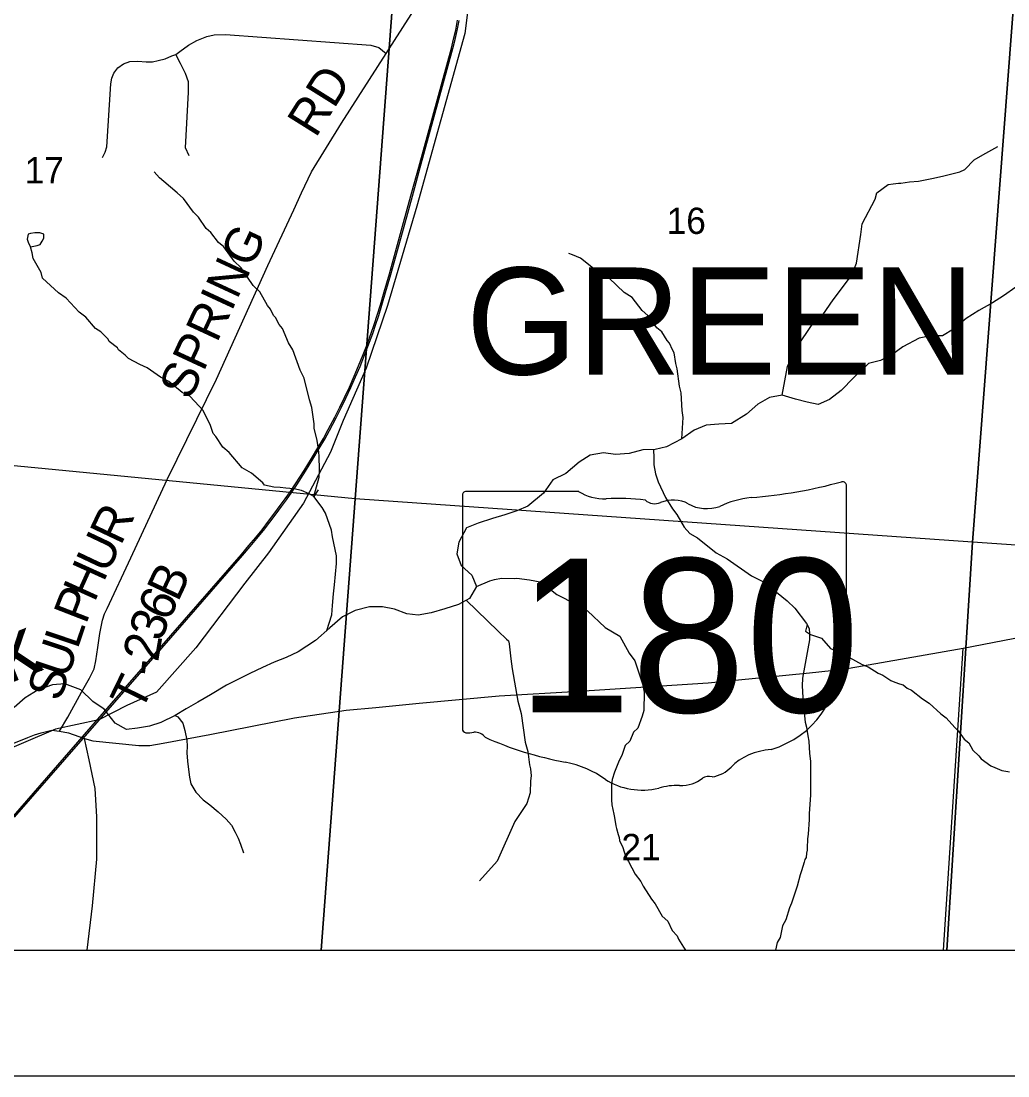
# Model space of a CAD drawing. Extents: x 0 to 42.5, y 0 to 22.
# Drawn here: x 2.796 to 3.582, y 14 to 14.84 of the extents above; entities that cross this region are included whole.
import ezdxf

# ---------------------------------------------------------------- set-up
doc = ezdxf.new("R2010")
doc.units = 0
for name, color, linetype in [('GM_X_County_Road', 7, 'Continuous'), ('GM_X_Interchange_Ramps', 7, 'Continuous'), ('GM_X_Minor_Lake', 7, 'Continuous'), ('GM_X_Minor_River', 7, 'Continuous'), ('GM_X_Minor_River_Text', 7, 'Continuous'), ('GM_X_Rail_Line', 7, 'Continuous'), ('GM_X_Section', 7, 'Continuous'), ('GM_X_Section_Text', 7, 'Continuous'), ('GM_X_State_Location', 7, 'Continuous'), ('GM_X_State_Route', 7, 'Continuous'), ('GM_X_State_Shield', 7, 'Continuous'), ('GM_X_Township_Road', 7, 'Continuous'), ('GM_X_Township_Road_Text', 7, 'Continuous'), ('GM_X_Township_Text', 7, 'Continuous'), ('GM_X_Unincorporated', 7, 'Continuous'), ('SH_Cut_Line', 7, 'Continuous'), ('SH_Data', 7, 'Continuous')]:
    doc.layers.add(name, color=color, linetype=linetype)

msp = doc.modelspace()

# ---------------------------------------------------------------- linework, layer by layer
at = {"layer": 'GM_X_County_Road'}
msp.add_lwpolyline([(2.84846, 14.1), (2.85274, 14.13543), (2.85614, 14.17249), (2.85609, 14.20615), (2.85479, 14.2288), (2.84994, 14.25157), (2.8463, 14.26864)], dxfattribs=at)
at = {"layer": 'GM_X_Interchange_Ramps'}
msp.add_lwpolyline([(4.44374, 15.85348), (3.72132, 15.90374), (3.70364, 15.90484), (3.68116, 15.90613), (3.63539, 15.91028), (3.54426, 15.91466), (3.50878, 15.91695), (3.47339, 15.91924), (3.14954, 15.94013), (2.52965, 15.98049), (2.1, 16.00757), (2.1, 14.1), (5.08492, 14.1)], dxfattribs=at)
at = {"layer": 'GM_X_Minor_Lake'}
for points in [[(2.80875, 14.66109), (2.81103, 14.66185), (2.81255, 14.66469), (2.81408, 14.66697), (2.81389, 14.67001), (2.81086, 14.67116), (2.80687, 14.67116), (2.80345, 14.6706), (2.80136, 14.67022), (2.80078, 14.66604), (2.80173, 14.663), (2.80324, 14.65996)], [(2.80324, 14.65996), (2.80875, 14.66109)]]:
    msp.add_lwpolyline(points, dxfattribs=at)
at = {"layer": 'GM_X_Minor_River'}
for points in [[(3.40207, 14.54193), (3.4063, 14.56478), (3.40898, 14.5697), (3.41205, 14.57595), (3.41263, 14.57727), (3.41397, 14.58031), (3.42584, 14.59828), (3.43424, 14.60582), (3.44247, 14.61792), (3.4572, 14.6372), (3.46123, 14.64705), (3.46456, 14.66983), (3.46555, 14.67838), (3.47591, 14.69788), (3.47745, 14.703), (3.48623, 14.70959), (3.49022, 14.71032), (3.4946, 14.71086), (3.4965, 14.71085), (3.50335, 14.71175), (3.51058, 14.71227), (3.52238, 14.71466), (3.53057, 14.7165), (3.54352, 14.71983), (3.54752, 14.7217), (3.55497, 14.72944), (3.56164, 14.73339), (3.57365, 14.73995)], [(3.03246, 14.46654), (3.02891, 14.46117), (3.03316, 14.47672), (3.03356, 14.48261), (3.03323, 14.49344), (3.03305, 14.49667), (3.03195, 14.50428), (3.03139, 14.50714), (3.02933, 14.51532), (3.02916, 14.51912), (3.02731, 14.53225), (3.02544, 14.53834), (3.02132, 14.55547), (3.01812, 14.56195), (3.01229, 14.57815), (3.00889, 14.58368), (3.004, 14.59512), (3.00135, 14.59817), (2.99852, 14.60389), (2.99682, 14.60542), (2.99436, 14.61038), (2.99209, 14.61325), (2.98586, 14.62412), (2.98056, 14.62929), (2.97111, 14.64342), (2.96543, 14.64859), (2.9573, 14.66004), (2.95294, 14.6635), (2.94689, 14.67152), (2.94329, 14.67477), (2.93724, 14.68375), (2.93308, 14.68776), (2.92532, 14.69865), (2.92002, 14.70306), (2.9096, 14.71206), (2.90619, 14.71512), (2.90183, 14.71971)], [(3.03938, 14.35457), (3.04334, 14.3672), (3.04375, 14.37442), (3.04455, 14.38391), (3.04553, 14.39094), (3.04694, 14.40803), (3.04696, 14.41411), (3.0438, 14.42914), (3.04306, 14.43447), (3.03836, 14.44799), (3.03572, 14.45257), (3.02891, 14.46117), (3.0253, 14.46347), (3.01904, 14.46599), (3.01296, 14.46736), (3.00669, 14.46797), (3.00212, 14.46839), (2.99718, 14.46861), (2.98977, 14.47018), (2.98844, 14.47209), (2.97935, 14.47994), (2.97195, 14.48399), (2.96154, 14.49641), (2.95643, 14.50062), (2.95095, 14.50902), (2.94887, 14.51151), (2.94642, 14.51856), (2.94472, 14.52161), (2.94077, 14.52981), (2.93755, 14.53325), (2.93035, 14.54109), (2.92409, 14.54398), (2.91348, 14.5528), (2.90684, 14.55626), (2.89622, 14.56375), (2.89033, 14.56645), (2.88142, 14.57126), (2.87877, 14.57394), (2.87346, 14.57816), (2.8727, 14.57968), (2.86588, 14.58467), (2.86513, 14.58657), (2.85944, 14.59231), (2.85508, 14.595), (2.84751, 14.60418), (2.84202, 14.60802), (2.83179, 14.61911), (2.82553, 14.62352), (2.81284, 14.63501), (2.81172, 14.63958), (2.80549, 14.65064), (2.80476, 14.65521), (2.80324, 14.65996)], [(3.32206, 14.50723), (3.32301, 14.52431), (3.32228, 14.52964), (3.32139, 14.5437), (3.32027, 14.54922), (3.31843, 14.56292), (3.3173, 14.5671), (3.31582, 14.57567), (3.3145, 14.57814), (3.31224, 14.58329), (3.31034, 14.58539), (3.306, 14.59226), (3.30221, 14.59552), (3.29502, 14.60526), (3.29048, 14.60928), (3.28253, 14.61979), (3.27608, 14.62364), (3.26415, 14.63512), (3.25561, 14.63974), (3.2414, 14.65105), (3.23494, 14.65375), (3.23209, 14.65472)], [(3.58805, 14.62785), (3.57812, 14.62109), (3.56935, 14.61546), (3.55867, 14.60946), (3.54837, 14.60308), (3.53842, 14.59442), (3.52965, 14.58917), (3.52054, 14.58925), (3.51103, 14.58742), (3.49806, 14.58031), (3.4889, 14.57392), (3.48013, 14.56943), (3.47062, 14.56723), (3.45914, 14.55592), (3.44881, 14.54574), (3.43964, 14.53859), (3.43049, 14.53448), (3.42177, 14.53645), (3.41268, 14.53881), (3.40207, 14.54193), (3.3918, 14.54012), (3.38265, 14.53487), (3.37348, 14.52696), (3.36164, 14.51946), (3.35139, 14.51878), (3.34151, 14.5181), (3.33198, 14.51399), (3.32206, 14.50723), (3.30986, 14.50087), (3.30073, 14.49866), (3.29085, 14.49836), (3.28019, 14.49541), (3.26918, 14.49474), (3.25969, 14.49595), (3.24905, 14.49414), (3.24027, 14.48851), (3.22957, 14.47947), (3.21928, 14.47462), (3.21198, 14.46403), (3.19936, 14.45349), (3.1906, 14.44976), (3.18109, 14.4468), (3.17119, 14.44384), (3.15977, 14.44013), (3.15063, 14.4364), (3.14446, 14.42505), (3.14287, 14.41556), (3.14621, 14.40641), (3.15489, 14.39874), (3.15861, 14.38959), (3.15284, 14.38013), (3.14407, 14.37526), (3.13341, 14.37193), (3.12237, 14.36859), (3.11211, 14.36678), (3.103, 14.36799), (3.09316, 14.37149), (3.08368, 14.37347), (3.07343, 14.37355), (3.06201, 14.3706), (3.05172, 14.36536), (3.04178, 14.3567), (3.03031, 14.34653), (3.01657, 14.33752), (3.00704, 14.33304), (2.99752, 14.32931), (2.98799, 14.32521), (2.97808, 14.32035), (2.96855, 14.31548), (2.9594, 14.311), (2.94681, 14.3035), (2.93651, 14.2975), (2.92736, 14.29225), (2.91858, 14.287), (2.90714, 14.28139), (2.89801, 14.27842), (2.8885, 14.27698), (2.87976, 14.27591), (2.87069, 14.28092), (2.86204, 14.29202), (2.85298, 14.29817), (2.84355, 14.30737), (2.83068, 14.31203), (2.8208, 14.31135), (2.80938, 14.30726), (2.79908, 14.30088), (2.79028, 14.29335)], [(3.29935, 14.49862), (3.29967, 14.49198), (3.29965, 14.48647), (3.30095, 14.47943), (3.30321, 14.47295), (3.30905, 14.46037), (3.31452, 14.45159), (3.31812, 14.44701), (3.32378, 14.4369), (3.32851, 14.43192), (3.33439, 14.42827), (3.34937, 14.41639), (3.3581, 14.41158), (3.37763, 14.39814), (3.38769, 14.39313), (3.40588, 14.37818), (3.41213, 14.37244), (3.4214, 14.36021), (3.42347, 14.35621), (3.42383, 14.35183), (3.42383, 14.3505), (3.42362, 14.34728), (3.42226, 14.34007), (3.42128, 14.33418), (3.41817, 14.31653), (3.41776, 14.31064), (3.41865, 14.29658), (3.4192, 14.29163), (3.4203, 14.28155), (3.42142, 14.27774), (3.42234, 14.27071), (3.42309, 14.26652), (3.42361, 14.25664), (3.42454, 14.25055), (3.42442, 14.22338), (3.42341, 14.20894), (3.42339, 14.20419), (3.42258, 14.19242), (3.42218, 14.18862), (3.42196, 14.1814), (3.42176, 14.17969), (3.42137, 14.17722), (3.42098, 14.174), (3.42002, 14.17229), (3.41944, 14.17021), (3.41732, 14.16319), (3.41616, 14.16016), (3.41384, 14.15105), (3.41268, 14.14707), (3.40941, 14.1374), (3.40787, 14.1338), (3.40479, 14.12432), (3.4021, 14.1194), (3.40035, 14.1101), (3.39805, 14.10613), (3.39654, 14.1)], [(3.15861, 14.38959), (3.16917, 14.39426), (3.17278, 14.39519), (3.1785, 14.39629), (3.18877, 14.39603), (3.19067, 14.39639), (3.20074, 14.395), (3.21062, 14.39303), (3.21233, 14.39111), (3.22237, 14.38325), (3.22788, 14.38055), (3.24021, 14.37401), (3.24685, 14.37016), (3.26106, 14.35695), (3.27263, 14.35022), (3.27999, 14.33668), (3.28472, 14.33057), (3.29072, 14.31209), (3.29203, 14.30543), (3.29177, 14.29099), (3.29042, 14.28644), (3.28696, 14.27696), (3.28352, 14.27357), (3.28064, 14.26656), (3.27682, 14.26316), (3.27431, 14.25501), (3.27201, 14.25123), (3.26836, 14.24194), (3.26662, 14.23587), (3.26603, 14.23189), (3.26598, 14.21972), (3.26635, 14.21573), (3.26784, 14.20831), (3.26839, 14.20565), (3.26951, 14.19918), (3.27007, 14.19708), (3.27138, 14.19213), (3.27213, 14.18985), (3.2725, 14.18738), (3.27514, 14.18185), (3.27739, 14.17423), (3.27966, 14.1706), (3.28475, 14.16069), (3.28948, 14.15476), (3.29136, 14.15114), (3.29778, 14.14084), (3.30081, 14.13701), (3.30628, 14.12728), (3.31102, 14.12307), (3.31441, 14.11583), (3.3182, 14.11162), (3.31933, 14.10895), (3.32329, 14.10246), (3.32498, 14.1)], [(3.15021, 14.37867), (3.17584, 14.35412), (3.18247, 14.34762), (3.18399, 14.34628), (3.18455, 14.34399), (3.18583, 14.33201), (3.18693, 14.32402), (3.19139, 14.29834), (3.19401, 14.28844), (3.19733, 14.26561), (3.19939, 14.25838), (3.20068, 14.24773), (3.20162, 14.24449), (3.20197, 14.23898), (3.20158, 14.23499), (3.20115, 14.2253), (3.19865, 14.21696), (3.18907, 14.20258), (3.17487, 14.17095), (3.16091, 14.15527)], [(3.42185, 14.35935), (3.42042, 14.35414), (3.4244, 14.35145), (3.43314, 14.34854), (3.44052, 14.34032), (3.45115, 14.33587), (3.45494, 14.33338), (3.46576, 14.3276), (3.47032, 14.32567), (3.47847, 14.32067), (3.48208, 14.31894), (3.48853, 14.31471), (3.49156, 14.31355), (3.49536, 14.31219), (3.4984, 14.31122), (3.50143, 14.30873), (3.50504, 14.307), (3.51376, 14.3001), (3.51907, 14.29683), (3.52835, 14.28821), (3.53252, 14.28496), (3.53953, 14.2775), (3.54218, 14.27463), (3.5469, 14.26813), (3.5505, 14.26526), (3.55371, 14.25934), (3.55845, 14.25494), (3.56053, 14.25246), (3.56811, 14.24689), (3.57134, 14.24554), (3.57685, 14.24322), (3.5816, 14.24243), (3.58293, 14.24204)], [(2.91858, 14.287), (2.92061, 14.28596), (2.92472, 14.28089), (2.92623, 14.275), (2.92793, 14.2674), (2.92811, 14.26246), (2.92791, 14.25733), (2.92847, 14.25068), (2.92922, 14.24403), (2.92997, 14.23775), (2.93091, 14.23243), (2.93489, 14.22597), (2.94077, 14.21988), (2.94607, 14.21569), (2.95271, 14.21016), (2.95916, 14.20445), (2.96333, 14.1997), (2.96636, 14.19399), (2.96882, 14.18924), (2.97052, 14.18448), (2.97298, 14.17764)]]:
    msp.add_lwpolyline(points, dxfattribs=at)
at = {"layer": 'GM_X_Rail_Line'}
for points in [[(3.15856, 14.90389), (3.14925, 14.82993), (3.11101, 14.6923), (3.08771, 14.61323), (3.07071, 14.56354), (3.05238, 14.52177), (3.04236, 14.4966), (3.02078, 14.45585), (2.99282, 14.41635), (2.97395, 14.39221), (2.93506, 14.34093), (2.90377, 14.30558), (2.87996, 14.29483), (2.85783, 14.28359)], [(2.78968, 14.2068), (2.85703, 14.28411), (2.97137, 14.41522), (2.97733, 14.42218), (2.98275, 14.4286), (2.98782, 14.43488), (2.99297, 14.44156), (2.99798, 14.44818), (3.0022, 14.454), (3.00615, 14.45942), (3.01036, 14.46537), (3.01436, 14.47124), (3.02138, 14.48208), (3.0272, 14.4915), (3.03228, 14.50006), (3.03656, 14.50742), (3.04043, 14.5145), (3.04565, 14.52439), (3.04959, 14.53228), (3.05347, 14.54017), (3.05735, 14.54846), (3.06109, 14.55702), (3.06463, 14.56524), (3.06818, 14.57426), (3.07085, 14.58109), (3.07473, 14.59144), (3.07693, 14.59819), (3.07948, 14.60575), (3.08202, 14.61383), (3.08503, 14.62414), (3.08911, 14.63847), (3.09963, 14.67652), (3.10713, 14.70358), (3.11262, 14.72355), (3.13855, 14.81813), (3.14028, 14.82547), (3.14195, 14.83262), (3.14349, 14.84043)], [(2.79059, 14.20601), (2.85794, 14.28333), (2.97228, 14.41444), (2.97825, 14.42141), (2.98367, 14.42784), (2.98877, 14.43414), (2.99393, 14.44084), (2.99895, 14.44747), (3.00317, 14.4533), (3.00712, 14.45873), (3.01134, 14.46469), (3.01536, 14.47058), (3.0224, 14.48144), (3.02823, 14.49088), (3.03332, 14.49946), (3.03761, 14.50683), (3.04149, 14.51393), (3.04672, 14.52385), (3.05067, 14.53175), (3.05456, 14.53966), (3.05844, 14.54797), (3.0622, 14.55654), (3.06575, 14.56478), (3.0693, 14.57383), (3.07198, 14.58066), (3.07586, 14.59104), (3.07807, 14.59781), (3.08062, 14.60538), (3.08317, 14.61349), (3.08618, 14.62381), (3.09027, 14.63814), (3.10079, 14.6762), (3.10829, 14.70327), (3.11378, 14.72323), (3.13971, 14.81783), (3.14145, 14.8252), (3.14313, 14.83237), (3.14467, 14.84021)], [(2.85783, 14.28359), (2.82334, 14.27594), (2.70308, 14.2249), (2.59128, 14.19074), (2.56697, 14.1766), (2.53031, 14.15072), (2.5038, 14.12969), (2.47486, 14.1)]]:
    msp.add_lwpolyline(points, dxfattribs=at)
at = {"layer": 'GM_X_Section'}
for points in [[(2.58723, 14.98757), (3.09918, 14.95159), (3.06197, 14.45953), (2.55405, 14.50856)], [(3.09918, 14.95159), (3.59088, 14.91475), (3.55348, 14.42497), (3.06197, 14.45953)], [(3.59088, 14.91475), (4.10606, 14.87895), (4.07019, 14.38934), (3.55348, 14.42497)]]:
    msp.add_lwpolyline(points, close=True, dxfattribs=at)
at = {"layer": 'GM_X_State_Route'}
for points in [[(3.07837, 14.29342), (3.11292, 14.29665), (3.17651, 14.30263), (3.24014, 14.30619), (3.34309, 14.31293), (3.42376, 14.32097), (3.45071, 14.32378), (3.54617, 14.34044), (3.61873, 14.3547), (3.77545, 14.3833), (3.81125, 14.38966)], [(2.48265, 14.16044), (2.4857, 14.16188), (2.49516, 14.16525), (2.51666, 14.17325), (2.66313, 14.21701), (2.70342, 14.23007), (2.75087, 14.24916), (2.80127, 14.26938), (2.80661, 14.27148), (2.81194, 14.27303), (2.82036, 14.27513), (2.82636, 14.27459), (2.83364, 14.27324), (2.8463, 14.26864), (2.85301, 14.26672), (2.88957, 14.26314), (2.89837, 14.26314), (2.90894, 14.26478), (2.94621, 14.27171), (3.0136, 14.28499), (3.05485, 14.29121), (3.07837, 14.29342)]]:
    msp.add_lwpolyline(points, dxfattribs=at)
at = {"layer": 'GM_X_State_Shield'}
for p, q in [((3.45313, 14.37278), (3.45313, 14.46991)), ((3.14732, 14.46211), (3.14732, 14.27643)), ((3.23989, 14.46531), (3.15033, 14.46531)), ((3.4531, 14.3728), (3.45313, 14.37278))]:
    msp.add_line(p, q, dxfattribs=at)
for centre, major_axis, start_param, end_param in [((3.34419, 14.71846), (0.32431, 0), 4.814394, 5.042369), ((3.44973, 14.47031), (0.0034, 0), 6.141152, 7.989035), ((3.15082, 14.46251), (0.00354, 0), 1.712693, 3.28349), ((3.26121, 14.48686), (0.03436, 0), 4.042523, 4.731795), ((3.27261, 14.36106), (0.12336, 0), 1.404758, 1.657858), ((3.30061, 14.46347), (0.00991, 0), 3.836095, 5.185415), ((3.31517, 14.44201), (0.02061, 0), 0.950623, 2.079405), ((3.34177, 14.47145), (0.02479, 0), 4.081561, 5.145723), ((3.38556, 14.40859), (0.06525, 0), 1.699011, 2.107814), ((3.45234, 14.36564), (0.00527, 0), 1.883978, 3.671073), ((3.44949, 14.3724), (0.00364, 0), 5.05454, 6.418171), ((3.41882, 14.35337), (0.03163, 0), 5.934695, 6.695948), ((3.46532, 14.33213), (0.02301, 0), 2.387724, 3.262537), ((3.36236, 14.31977), (0.08112, 0), 5.101752, 6.440018), ((3.15085, 14.27602), (0.00357, 0), 3.00124, 4.508301), ((3.15139, 14.29502), (0.02728, 0), 4.665946, 4.897461), ((3.15697, 14.26571), (0.00984, 0), 0.519207, 1.627899), ((3.28115, 14.43255), (0.2342, 0), 4.195997, 4.488961), ((3.39656, 14.2243), (0.04443, 0), 1.647645, 2.488434), ((3.21132, 14.19301), (0.07328, 0), 0.823519, 1.323587), ((3.34028, 14.25843), (0.02621, 0), 4.937069, 5.64225), ((3.29058, 14.26479), (0.0465, 0), 4.026481, 4.996735), ((3.32084, 14.25089), (0.02477, 0), 4.691044, 5.507374), ((3.34325, 14.2329), (0.00698, 0), 1.147584, 2.315152), ((3.31744, 14.20059), (0.03821, 0), 1.495662, 1.94098)]:
    msp.add_ellipse(centre, major_axis=major_axis, ratio=0.8, start_param=start_param, end_param=end_param, dxfattribs=at)
at = {"layer": 'GM_X_Township_Road'}
msp.add_line((3.53029, 14.1), (3.54617, 14.34044), dxfattribs=at)
for points in [[(2.82636, 14.27459), (2.83307, 14.28571), (2.844, 14.30546), (2.85033, 14.31658), (2.85397, 14.32406), (2.8555, 14.33039), (2.85685, 14.34113), (2.85857, 14.35225), (2.86068, 14.3628), (2.86222, 14.36798), (2.86433, 14.37219), (2.88322, 14.41235), (2.91231, 14.47469), (2.95147, 14.55468), (2.99239, 14.64529), (3.01311, 14.68954), (3.01929, 14.7031), (3.02725, 14.71967), (3.05108, 14.75853), (3.0867, 14.81405), (3.13311, 14.88669)], [(2.9224, 14.81549), (2.9292, 14.82056), (2.93571, 14.82437), (2.9438, 14.82755), (2.9497, 14.82882), (2.95857, 14.82898), (3.07432, 14.82072), (3.08067, 14.81882), (3.0867, 14.81405)], [(2.86061, 14.73118), (2.86283, 14.7353), (2.8641, 14.73975), (2.86744, 14.78992), (2.86823, 14.79437), (2.86982, 14.79834), (2.87299, 14.80246), (2.87744, 14.8058), (2.88236, 14.80754), (2.88871, 14.80786), (2.89538, 14.80738), (2.90046, 14.80738), (2.90507, 14.80834), (2.91062, 14.80961), (2.91602, 14.81199), (2.9192, 14.8131), (2.9224, 14.81549)], [(2.92967, 14.7326), (2.92666, 14.73895), (2.9292, 14.78309), (2.92904, 14.79135), (2.92682, 14.79817), (2.92285, 14.80596), (2.9192, 14.8131)]]:
    msp.add_lwpolyline(points, dxfattribs=at)
at = {"layer": 'GM_X_Unincorporated'}
for points in [[(2.52705, 14.1), (3.03478, 14.1), (3.06197, 14.45953), (2.55405, 14.50856)], [(3.03478, 14.1), (3.53318, 14.1), (3.55348, 14.42497), (3.06197, 14.45953)], [(3.53318, 14.1), (4.04905, 14.1), (4.07019, 14.38934), (3.55348, 14.42497)]]:
    msp.add_lwpolyline(points, close=True, dxfattribs=at)
at = {"layer": 'SH_Cut_Line'}
msp.add_lwpolyline([(4.44374, 15.85348), (3.72132, 15.90374), (3.70364, 15.90484), (3.68116, 15.90613), (3.63539, 15.91028), (3.54426, 15.91466), (3.50878, 15.91695), (3.47339, 15.91924), (3.14954, 15.94013), (2.52965, 15.98049), (2.1, 16.00757), (2.1, 14.1), (8.06989, 14.1)], dxfattribs=at)
at = {"layer": 'SH_Data'}
for p, q in [((2.1, 14.1), (8.9, 14.1)), ((2, 14), (9, 14))]:
    msp.add_line(p, q, dxfattribs=at)

# ---------------------------------------------------------------- texts
at = {"layer": 'GM_X_Minor_River_Text'}
msp.add_text('Kinnikinnick', height=0.0473477, rotation=22.00242, dxfattribs=at).set_placement((2.50424, 14.19818))
at = {"layer": 'GM_X_Section_Text'}
for s, p in [('17', (2.79876, 14.71058)), ('16', (3.31001, 14.67032)), ('21', (3.27397, 14.17173))]:
    msp.add_text(s, height=0.020928, rotation=0.00001, dxfattribs=at).set_placement(p)
at = {"layer": 'GM_X_State_Location'}
for s in ['s', 'r']:
    msp.add_text(s, height=0.0000947, dxfattribs=at).set_placement((3.29094, 14.29691))
msp.add_text('180', height=0.0000947, rotation=0.00001, dxfattribs=at).set_placement((3.25751, 14.29002))
at = {"layer": 'GM_X_State_Shield'}
msp.add_text('180', height=0.122327, dxfattribs=at).set_placement((3.19088, 14.28952))
at = {"layer": 'GM_X_Township_Road_Text'}
for s, height, rotation, p in [('RD', 0.028409, 57.94337, (3.03045, 14.74608)), ('SPRING', 0.028409, 65.08528, (2.93046, 14.53703)), ('R', 0.02841, 64.63766, (2.87523, 14.42157)), ('U', 0.02841, 64.64221, (2.86452, 14.39898)), ('H', 0.02841, 65.64136, (2.85426, 14.37633)), ('B', 0.02841, 64.76688, (2.92068, 14.37657)), ('P', 0.02841, 68.77827, (2.84749, 14.35884)), ('6', 0.02841, 64.78724, (2.91323, 14.36074)), ('3', 0.02841, 70.04267, (2.90752, 14.34493)), ('L', 0.02841, 71.26148, (2.84077, 14.33902)), ('U', 0.02841, 71.665, (2.83292, 14.31534)), ('2', 0.02841, 80.2793, (2.90491, 14.32898)), ('-', 0.02841, 83.44895, (2.90363, 14.3178)), ('S', 0.02841, 71.66121, (2.82689, 14.29715)), ('T', 0.02841, 63.97927, (2.89137, 14.28865))]:
    msp.add_text(s, height=height, rotation=rotation, dxfattribs=at).set_placement(p)
at = {"layer": 'GM_X_Township_Text'}
msp.add_text('GREEN', height=0.085227, rotation=0.00001, dxfattribs=at).set_placement((3.15024, 14.5584))

doc.saveas('drawing.dxf')
